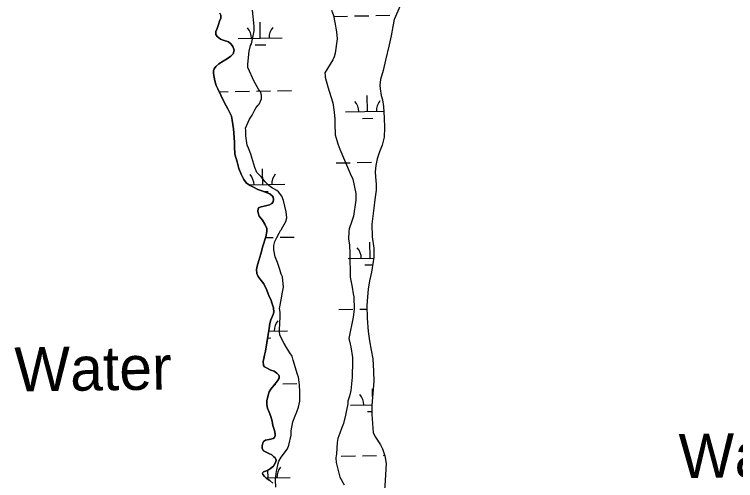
# Model space of a CAD drawing. Extents: x 3903937 to 3942190, y 260677 to 286651.
# Drawn here: x 3915933 to 3917570, y 267536 to 268594 of the extents above; entities that cross this region are included whole.
import ezdxf

# ---------------------------------------------------------------- set-up
doc = ezdxf.new("R2010")
doc.units = 0
for name, color, linetype in [('V-RIVR-IDEN', 7, 'Continuous'), ('V-SITE-VEGE', 7, 'Continuous'), ('V-TOPO-SHOR', 7, 'Continuous'), ('V-WETL-SWMP', 7, 'Continuous')]:
    doc.layers.add(name, color=color, linetype=linetype)

msp = doc.modelspace()

# ---------------------------------------------------------------- linework, layer by layer
at = {"layer": 'V-SITE-VEGE'}
for points in [[(3916534.7, 267926.7), (3916538.9, 267949.7), (3916540.5, 267959.5), (3916543.6, 267974.8), (3916541.1, 267998.4), (3916538.6, 268004.5), (3916535, 268014.8), (3916530, 268031.2), (3916524.4, 268044), (3916521.9, 268059.9), (3916522, 268069.6), (3916523, 268075.2), (3916524, 268078.3), (3916528.2, 268088), (3916533.9, 268097.7), (3916536.9, 268103.3), (3916538.5, 268105.3), (3916548.8, 268124.2), (3916550.9, 268132.4), (3916549.9, 268145.7), (3916543.4, 268171.9), (3916539.8, 268181.1), (3916532.2, 268191.4), (3916528.6, 268194.4), (3916516.4, 268201.1), (3916510.2, 268205.3), (3916502.1, 268214), (3916496.5, 268220.7), (3916493.9, 268224.3), (3916483.2, 268235.1), (3916478.2, 268246.3), (3916469.1, 268277.1), (3916464, 268290.4), (3916461, 268297.1), (3916458, 268318.1), (3916458, 268331.4), (3916457.5, 268335.5), (3916466.3, 268356.4), (3916472.5, 268365.1), (3916478.7, 268377.4), (3916481.8, 268382.5), (3916485.9, 268388.1), (3916488.5, 268390.1), (3916493.6, 268402.4), (3916493.7, 268410.6), (3916491.7, 268418.3), (3916490.1, 268419.8), (3916487.1, 268424.4), (3916477.4, 268441.3), (3916462.7, 268473.7), (3916462.8, 268480.8), (3916465.4, 268510.5), (3916468.6, 268523.3), (3916470.6, 268527.4), (3916476.9, 268556.5), (3916476.9, 268567.3), (3916473.5, 268603.6)], [(3916652.6, 268603.4), (3916657.2, 268591.6), (3916660.2, 268575.2), (3916663.7, 268554.2), (3916665.2, 268538.8), (3916660.9, 268506.1), (3916658.8, 268497.9), (3916655.2, 268490.8), (3916643.4, 268471.4), (3916637.7, 268461.2), (3916638.2, 268455), (3916638.2, 268451.4), (3916644.2, 268429.9), (3916650.8, 268407.4), (3916655.3, 268393), (3916658.8, 268372), (3916659.8, 268356.1), (3916659.8, 268345.4), (3916661.2, 268320.3), (3916665.2, 268305.5), (3916667.2, 268300.3), (3916671.8, 268288), (3916695.1, 268232.7), (3916700.7, 268220.3), (3916707.7, 268187.6), (3916707.7, 268172.7), (3916702.4, 268135.9), (3916698.3, 268124.6), (3916692.6, 268107.3), (3916691.5, 268101.6), (3916691.4, 268083.7), (3916693.4, 268070.9), (3916694.4, 268050.4), (3916694.7, 267997.7), (3916699.2, 267975.2), (3916701.7, 267959.8), (3916703.2, 267952.7), (3916704.1, 267925), (3916702, 267906.6), (3916692, 267858.5), (3916694.6, 267845.7), (3916696.6, 267839.6), (3916700.1, 267815.5), (3916700.5, 267795.5), (3916699.4, 267782.7), (3916699.4, 267770.5), (3916696.7, 267740.3), (3916693.6, 267727.5), (3916689.9, 267716.2), (3916689.4, 267710.1)], [(3916526.4, 267521.4), (3916525.4, 267537.3), (3916525.9, 267545), (3916528, 267557.2), (3916528.6, 267560.8), (3916531.2, 267574.6), (3916533.3, 267580.2), (3916538.4, 267589.4), (3916552.3, 267608.3), (3916555.9, 267616.5), (3916561.1, 267639.5), (3916560.7, 267645.6), (3916560.7, 267649.2), (3916564.8, 267669.2), (3916570, 267683), (3916573.6, 267692.2), (3916577.3, 267702.4), (3916580.4, 267716.2), (3916581, 267727.4), (3916580.5, 267733.6), (3916581, 267737.7), (3916580, 267753.6), (3916577.5, 267770.5), (3916575.5, 267776.6), (3916565.9, 267809.4), (3916563.4, 267818.6), (3916557.8, 267825.8), (3916550.7, 267838.1), (3916545.1, 267847.4), (3916534.9, 267866.3), (3916534.5, 267874.5), (3916534.5, 267878.1), (3916536.1, 267907.8), (3916535.7, 267918.5), (3916534.7, 267926.7)], [(3916689.4, 267710.1), (3916686.8, 267695.8), (3916684.2, 267684.5), (3916680, 267665.6), (3916675.3, 267654.4), (3916671.2, 267643.6), (3916667.1, 267631.4), (3916665.5, 267622.7), (3916663.8, 267597.1), (3916662.3, 267587.9), (3916663.2, 267577.1), (3916671.8, 267543.8), (3916681, 267526.4)]]:
    msp.add_lwpolyline(points, dxfattribs=at)
at = {"layer": 'V-TOPO-SHOR'}
for points in [[(3916399.3, 268597), (3916401.7, 268592), (3916401.1, 268585.1), (3916398.7, 268578.9), (3916396.1, 268570.8), (3916392.9, 268561.8), (3916390.4, 268555), (3916389.9, 268548.4), (3916392.7, 268543.8), (3916400.6, 268537.8), (3916406.3, 268535.3), (3916418.4, 268532), (3916425, 268526), (3916428.9, 268520.9), (3916431.6, 268513), (3916429.4, 268504.5), (3916424.1, 268499.5), (3916416.5, 268494.1), (3916396.5, 268481.4), (3916390.1, 268475.3), (3916386.3, 268470.2), (3916384.5, 268466), (3916384.8, 268459.9), (3916387.6, 268443), (3916391.1, 268432.6), (3916394.4, 268424.8), (3916401.3, 268410.4), (3916409.8, 268393.6), (3916417, 268379.8), (3916425.6, 268362.8), (3916427, 268354), (3916428.9, 268343.7), (3916430.2, 268334.4), (3916431.8, 268314.5), (3916432.1, 268303), (3916432.2, 268294.4), (3916433.4, 268276.6), (3916438.1, 268259), (3916442.3, 268244), (3916447.3, 268231.3), (3916453.7, 268219.3), (3916459.7, 268211.1), (3916467.9, 268206), (3916475.3, 268201.7), (3916485.2, 268196.4), (3916494.5, 268193.5), (3916512.7, 268186.9), (3916518.3, 268181.5), (3916519.8, 268179.2), (3916521.2, 268174.2), (3916520, 268168.9), (3916517, 268164.7), (3916511.6, 268162.1), (3916500, 268158.8), (3916492.8, 268157.1), (3916487.1, 268154.6), (3916486, 268152.7), (3916485.4, 268147.4), (3916485.8, 268143.5), (3916488.6, 268136.4), (3916496, 268126.7), (3916501.1, 268118.1), (3916505.4, 268108.2), (3916505.5, 268101.2), (3916503.2, 268089), (3916496.8, 268068.2)], [(3916496.8, 268068.2), (3916492.4, 268050.3), (3916487.4, 268035.1), (3916483.5, 268022.4), (3916482.4, 268015.3), (3916482.7, 268006.3), (3916485.8, 267999.5), (3916492.8, 267990), (3916498.6, 267982.3), (3916505.9, 267968.1), (3916511.4, 267954), (3916514.5, 267946.8), (3916518.1, 267937.3), (3916520.8, 267928), (3916521.6, 267918.3), (3916520.5, 267913), (3916517.9, 267907.3), (3916515, 267900.6), (3916512.8, 267892.2), (3916510.7, 267880.8), (3916509.1, 267867.4), (3916502.6, 267829.9), (3916500.6, 267820.6), (3916499.1, 267813), (3916497.6, 267806.1), (3916497.9, 267797.1), (3916500.2, 267793.9), (3916515.2, 267786.7), (3916522.2, 267784.1), (3916528.4, 267779.9), (3916533, 267775.3), (3916533.9, 267772.9), (3916533.6, 267768.6), (3916529.9, 267762.2), (3916521.7, 267751.5), (3916515.2, 267743.7), (3916511, 267737.2), (3916508.6, 267729.8), (3916505.7, 267716.9), (3916505.8, 267708.9), (3916507, 267700.3), (3916510.7, 267691.4), (3916514.8, 267681.2), (3916517.5, 267670.6), (3916519.7, 267660.8), (3916523.1, 267650), (3916524.6, 267641.2), (3916524.6, 267638), (3916523.4, 267633.6), (3916519.9, 267631.6), (3916511.2, 267629.5), (3916502.7, 267627.5), (3916498.4, 267624.9), (3916496.7, 267621), (3916495.2, 267614.6), (3916495.1, 267608.7), (3916498.4, 267603.7), (3916510.6, 267597.4), (3916516.8, 267594.2), (3916522, 267590.2), (3916524.9, 267587.8), (3916526.6, 267582.5), (3916526.2, 267578.3), (3916520.6, 267568.7), (3916514.3, 267563.2), (3916507.2, 267559), (3916498.5, 267555.7), (3916496.6, 267554.6), (3916495.9, 267552.7), (3916496.6, 267550.2), (3916500.2, 267545.7), (3916504.5, 267541.2), (3916512.9, 267536.1), (3916519.5, 267530.5)]]:
    msp.add_lwpolyline(points, dxfattribs=at)
at = {"layer": 'V-WETL-SWMP'}
for p, q in [((3916808.3, 268613.1), (3916794.7, 268582.2)), ((3916398.7, 268578.9), (3916401.1, 268585.1)), ((3916401.7, 268592), (3916399.3, 268597)), ((3916401.1, 268585.1), (3916401.7, 268592)), ((3916657.1, 268589.5), (3916689.1, 268590.1)), ((3916705.1, 268590.3), (3916737.1, 268590.9)), ((3916753.1, 268591.2), (3916785.1, 268591.8)), ((3916794.7, 268582.2), (3916791.5, 268566.8)), ((3916392.9, 268561.8), (3916396.1, 268570.8)), ((3916396.1, 268570.8), (3916398.7, 268578.9)), ((3916490.9, 268540.1), (3916490.3, 268576.1)), ((3916791.5, 268566.8), (3916787.9, 268544.9)), ((3916389.9, 268548.4), (3916390.4, 268555)), ((3916392.7, 268543.8), (3916389.9, 268548.4)), ((3916390.4, 268555), (3916392.9, 268561.8)), ((3916400.6, 268537.8), (3916392.7, 268543.8)), ((3916406.3, 268535.3), (3916400.6, 268537.8)), ((3916418.4, 268532), (3916406.3, 268535.3)), ((3916425, 268526), (3916418.4, 268532)), ((3916440.9, 268539.3), (3916540.9, 268541)), ((3916787.9, 268544.9), (3916783.2, 268524.5)), ((3916428.9, 268520.9), (3916425, 268526)), ((3916431.6, 268513), (3916428.9, 268520.9)), ((3916479.2, 268524.5), (3916503.2, 268524.9)), ((3916783.2, 268524.5), (3916775, 268490.4)), ((3916416.5, 268494.1), (3916424.1, 268499.5)), ((3916424.1, 268499.5), (3916429.4, 268504.5)), ((3916429.4, 268504.5), (3916431.6, 268513)), ((3916396.5, 268481.4), (3916416.5, 268494.1)), ((3916775, 268490.4), (3916769.6, 268466.7)), ((3916384.5, 268466), (3916386.3, 268470.2)), ((3916386.3, 268470.2), (3916390.1, 268475.3)), ((3916390.1, 268475.3), (3916396.5, 268481.4)), ((3916769.6, 268466.7), (3916763.4, 268445.8)), ((3916384.8, 268459.9), (3916384.5, 268466)), ((3916387.6, 268443), (3916384.8, 268459.9)), ((3916391.1, 268432.6), (3916387.6, 268443)), ((3916763.4, 268445.8), (3916762.1, 268433.6)), ((3916394.4, 268424.8), (3916391.1, 268432.6)), ((3916401.3, 268410.4), (3916394.4, 268424.8)), ((3916397.5, 268418.4), (3916418.2, 268418.8)), ((3916434.2, 268419), (3916466.2, 268419.6)), ((3916482.2, 268419.9), (3916514.2, 268420.5)), ((3916530.2, 268420.7), (3916562.1, 268421.3)), ((3916762.1, 268433.6), (3916762.7, 268424.7)), ((3916762.7, 268424.7), (3916765.6, 268410.1)), ((3916409.8, 268393.6), (3916401.3, 268410.4)), ((3916734.3, 268373.6), (3916733.7, 268409.6)), ((3916765.6, 268410.1), (3916768.1, 268400.4)), ((3916417, 268379.8), (3916409.8, 268393.6)), ((3916768.1, 268400.4), (3916770.6, 268385.2)), ((3916770.6, 268385.2), (3916772.3, 268358.9)), ((3916425.6, 268362.8), (3916417, 268379.8)), ((3916684.3, 268372.7), (3916771.3, 268374.2)), ((3916427, 268354), (3916425.6, 268362.8)), ((3916428.9, 268343.7), (3916427, 268354)), ((3916722.6, 268357.9), (3916746.6, 268358.4)), ((3916772.3, 268358.9), (3916773, 268336.2)), ((3916430.2, 268334.4), (3916428.9, 268343.7)), ((3916773, 268336.2), (3916771.9, 268315.2)), ((3916431.8, 268314.5), (3916430.2, 268334.4)), ((3916432.1, 268303), (3916431.8, 268314.5)), ((3916432.2, 268294.4), (3916432.1, 268303)), ((3916771.9, 268315.2), (3916767.5, 268296.9)), ((3916433.4, 268276.6), (3916432.2, 268294.4)), ((3916767.5, 268296.9), (3916761.1, 268282.3)), ((3916438.1, 268259), (3916433.4, 268276.6)), ((3916761.1, 268282.3), (3916756.1, 268266.5)), ((3916442.3, 268244), (3916438.1, 268259)), ((3916663, 268256.9), (3916695, 268257.4)), ((3916711, 268257.7), (3916743, 268258.3)), ((3916756.1, 268266.5), (3916752.9, 268250.7)), ((3916447.3, 268231.3), (3916442.3, 268244)), ((3916496.7, 268207.5), (3916496.1, 268243.5)), ((3916752.9, 268250.7), (3916751.8, 268236.9)), ((3916453.7, 268219.3), (3916447.3, 268231.3)), ((3916751.8, 268236.9), (3916752.4, 268225.1)), ((3916752.4, 268225.1), (3916754.1, 268208.9)), ((3916459.7, 268211.1), (3916453.7, 268219.3)), ((3916467.9, 268206), (3916459.7, 268211.1)), ((3916466.3, 268207), (3916546.7, 268208.4)), ((3916475.3, 268201.7), (3916467.9, 268206)), ((3916754.1, 268208.9), (3916753.8, 268195.4)), ((3916485.2, 268196.4), (3916475.3, 268201.7)), ((3916494.5, 268193.5), (3916485.2, 268196.4)), ((3916512.7, 268186.9), (3916494.5, 268193.5)), ((3916498.5, 268192.1), (3916509, 268192.3)), ((3916753.8, 268195.4), (3916751, 268173.9)), ((3916518.3, 268181.5), (3916512.7, 268186.9)), ((3916519.8, 268179.2), (3916518.3, 268181.5)), ((3916521.2, 268174.2), (3916519.8, 268179.2)), ((3916520, 268168.9), (3916521.2, 268174.2)), ((3916751, 268173.9), (3916748.5, 268154.4)), ((3916487.1, 268154.6), (3916492.8, 268157.1)), ((3916492.8, 268157.1), (3916500, 268158.8)), ((3916500, 268158.8), (3916511.6, 268162.1)), ((3916511.6, 268162.1), (3916517, 268164.7)), ((3916517, 268164.7), (3916520, 268168.9)), ((3916485.4, 268147.4), (3916486, 268152.7)), ((3916485.8, 268143.5), (3916485.4, 268147.4)), ((3916488.6, 268136.4), (3916485.8, 268143.5)), ((3916486, 268152.7), (3916487.1, 268154.6)), ((3916748.5, 268154.4), (3916743.8, 268117.7)), ((3916496, 268126.7), (3916488.6, 268136.4)), ((3916501.1, 268118.1), (3916496, 268126.7)), ((3916505.4, 268108.2), (3916501.1, 268118.1)), ((3916505.5, 268101.2), (3916505.4, 268108.2)), ((3916743.8, 268117.7), (3916745.1, 268089)), ((3916503.2, 268089), (3916505.5, 268101.2)), ((3916496.8, 268068.2), (3916503.2, 268089)), ((3916502.7, 268087.5), (3916520, 268087.8)), ((3916536, 268088.1), (3916568, 268088.7)), ((3916740.2, 268041), (3916739.6, 268077)), ((3916745.1, 268089), (3916748.4, 268063.7)), ((3916492.4, 268050.3), (3916496.8, 268068.2)), ((3916748.4, 268063.7), (3916748.5, 268042.2)), ((3916487.4, 268035.1), (3916492.4, 268050.3)), ((3916690.2, 268040.1), (3916748.3, 268041.1)), ((3916748.5, 268042.2), (3916747.4, 268032.9)), ((3916483.5, 268022.4), (3916487.4, 268035.1)), ((3916728.5, 268025.3), (3916746.2, 268025.6)), ((3916747.4, 268032.9), (3916743.4, 268008.8)), ((3916482.4, 268015.3), (3916483.5, 268022.4)), ((3916482.7, 268006.3), (3916482.4, 268015.3)), ((3916743.4, 268008.8), (3916738.6, 267989.1)), ((3916485.8, 267999.5), (3916482.7, 268006.3)), ((3916492.8, 267990), (3916485.8, 267999.5)), ((3916498.6, 267982.3), (3916492.8, 267990)), ((3916505.9, 267968.1), (3916498.6, 267982.3)), ((3916738.6, 267989.1), (3916735.9, 267970.2)), ((3916511.4, 267954), (3916505.9, 267968.1)), ((3916735.9, 267970.2), (3916734.3, 267952.8)), ((3916514.5, 267946.8), (3916511.4, 267954)), ((3916518.1, 267937.3), (3916514.5, 267946.8)), ((3916734.3, 267952.8), (3916733, 267933.6)), ((3916520.8, 267928), (3916518.1, 267937.3)), ((3916521.6, 267918.3), (3916520.8, 267928)), ((3916733, 267933.6), (3916733.3, 267904.8)), ((3916517.9, 267907.3), (3916520.5, 267913)), ((3916520.5, 267913), (3916521.6, 267918.3)), ((3916668.8, 267924.3), (3916700.8, 267924.8)), ((3916716.8, 267925.1), (3916733.1, 267925.4)), ((3916512.8, 267892.2), (3916515, 267900.6)), ((3916515, 267900.6), (3916517.9, 267907.3)), ((3916733.3, 267904.8), (3916735.9, 267874.6)), ((3916509.1, 267867.4), (3916510.7, 267880.8)), ((3916510.7, 267880.8), (3916512.8, 267892.2)), ((3916502.6, 267829.9), (3916509.1, 267867.4)), ((3916510, 267875), (3916552.6, 267875.8)), ((3916735.9, 267874.6), (3916738.6, 267853.2)), ((3916507.8, 267859.5), (3916514.9, 267859.7)), ((3916738.6, 267853.2), (3916742.3, 267831.7)), ((3916500.6, 267820.6), (3916502.6, 267829.9)), ((3916742.3, 267831.7), (3916746.1, 267812.7)), ((3916497.6, 267806.1), (3916499.1, 267813)), ((3916499.1, 267813), (3916500.6, 267820.6)), ((3916746.1, 267812.7), (3916748.2, 267784.1)), ((3916497.9, 267797.1), (3916497.6, 267806.1)), ((3916500.2, 267793.9), (3916497.9, 267797.1)), ((3916515.2, 267786.7), (3916500.2, 267793.9)), ((3916522.2, 267784.1), (3916515.2, 267786.7)), ((3916528.4, 267779.9), (3916522.2, 267784.1)), ((3916533, 267775.3), (3916528.4, 267779.9)), ((3916748.2, 267784.1), (3916748.7, 267760.8)), ((3916529.9, 267762.2), (3916533.6, 267768.6)), ((3916533.9, 267772.9), (3916533, 267775.3)), ((3916533.6, 267768.6), (3916533.9, 267772.9)), ((3916515.2, 267743.7), (3916521.7, 267751.5)), ((3916521.7, 267751.5), (3916529.9, 267762.2)), ((3916524.5, 267755.2), (3916525.9, 267755.2)), ((3916541.9, 267755.5), (3916573.9, 267756.1)), ((3916748.7, 267760.8), (3916746.6, 267734.5)), ((3916508.6, 267729.8), (3916511, 267737.2)), ((3916511, 267737.2), (3916515.2, 267743.7)), ((3916746.6, 267734.5), (3916743.7, 267706.7)), ((3916745.7, 267726.1), (3916745.4, 267744.3)), ((3916505.7, 267716.9), (3916508.6, 267729.8)), ((3916505.8, 267708.9), (3916505.7, 267716.9)), ((3916507, 267700.3), (3916505.8, 267708.9)), ((3916510.7, 267691.4), (3916507, 267700.3)), ((3916696, 267707.5), (3916743.9, 267708.3)), ((3916743.7, 267706.7), (3916744, 267686.7)), ((3916514.8, 267681.2), (3916510.7, 267691.4)), ((3916517.5, 267670.6), (3916514.8, 267681.2)), ((3916734.3, 267692.7), (3916743.9, 267692.9)), ((3916744, 267686.7), (3916747.4, 267644.8)), ((3916519.6, 267660.8), (3916517.5, 267670.6)), ((3916523.1, 267650), (3916519.6, 267660.8)), ((3916524.6, 267641.2), (3916523.1, 267650)), ((3916519.9, 267631.6), (3916523.4, 267633.6)), ((3916523.4, 267633.6), (3916524.6, 267638)), ((3916524.6, 267638), (3916524.6, 267641.2)), ((3916747.4, 267644.8), (3916752.3, 267634.9)), ((3916752.3, 267634.9), (3916763.5, 267617.5)), ((3916495.2, 267614.6), (3916496.7, 267621)), ((3916496.7, 267621), (3916498.4, 267624.9)), ((3916498.4, 267624.9), (3916502.7, 267627.5)), ((3916502.7, 267627.5), (3916511.2, 267629.5)), ((3916511.2, 267629.5), (3916519.9, 267631.6)), ((3916763.5, 267617.5), (3916768.2, 267608)), ((3916495.1, 267608.7), (3916495.2, 267614.6)), ((3916498.4, 267603.7), (3916495.1, 267608.7)), ((3916510.6, 267597.4), (3916498.4, 267603.7)), ((3916768.2, 267608), (3916773.3, 267592.6)), ((3916516.8, 267594.2), (3916510.6, 267597.4)), ((3916522, 267590.2), (3916516.8, 267594.2)), ((3916524.9, 267587.8), (3916522, 267590.2)), ((3916526.6, 267582.5), (3916524.9, 267587.8)), ((3916674.7, 267591.6), (3916706.7, 267592.2)), ((3916722.7, 267592.5), (3916754.7, 267593)), ((3916770.7, 267593.3), (3916773, 267593.4)), ((3916773.3, 267592.6), (3916776.6, 267575.2)), ((3916514.3, 267563.2), (3916520.6, 267568.7)), ((3916520.6, 267568.7), (3916526.2, 267578.3)), ((3916526.2, 267578.3), (3916526.6, 267582.5)), ((3916776.6, 267575.2), (3916774.2, 267536.3)), ((3916495.9, 267552.7), (3916496.6, 267554.6)), ((3916496.6, 267550.2), (3916495.9, 267552.7)), ((3916496.6, 267554.6), (3916498.5, 267555.7)), ((3916500.2, 267545.7), (3916496.6, 267550.2)), ((3916498.5, 267555.7), (3916507.2, 267559)), ((3916507.2, 267559), (3916514.3, 267563.2)), ((3916508.5, 267542.3), (3916508.2, 267559.6)), ((3916504.5, 267541.2), (3916500.2, 267545.7)), ((3916503.6, 267542.2), (3916558.4, 267543.1)), ((3916512.9, 267536.1), (3916504.5, 267541.2)), ((3916774.2, 267536.3), (3916771.7, 267503.5))]:
    msp.add_line(p, q, dxfattribs=at)
for centre, start, end in [((3916435.6, 268539.6), 0.2366, 41.7802), ((3916546.1, 268541.6), 140.2366, 181.7802), ((3916679.1, 268373.1), 0.2366, 41.7802), ((3916789.6, 268375), 140.2366, 181.7802), ((3916441.5, 268207), 0.2366, 41.7802), ((3916552, 268209), 140.2366, 181.7802), ((3916684.9, 268040.5), 0.2366, 41.7802), ((3916557.8, 267876.3), 140.2366, 181.7802), ((3916690.8, 267707.8), 0.2366, 41.7802), ((3916563.7, 267543.7), 140.2366, 181.7802)]:
    msp.add_arc(centre, 35.2, start, end, dxfattribs=at)

# ---------------------------------------------------------------- texts
at = {"layer": 'V-RIVR-IDEN'}
for p in [(3915933.8, 267738), (3917441.4, 267541.7)]:
    msp.add_text('Water', height=100, rotation=0.8107, dxfattribs=at).set_placement(p)

doc.saveas('drawing.dxf')
